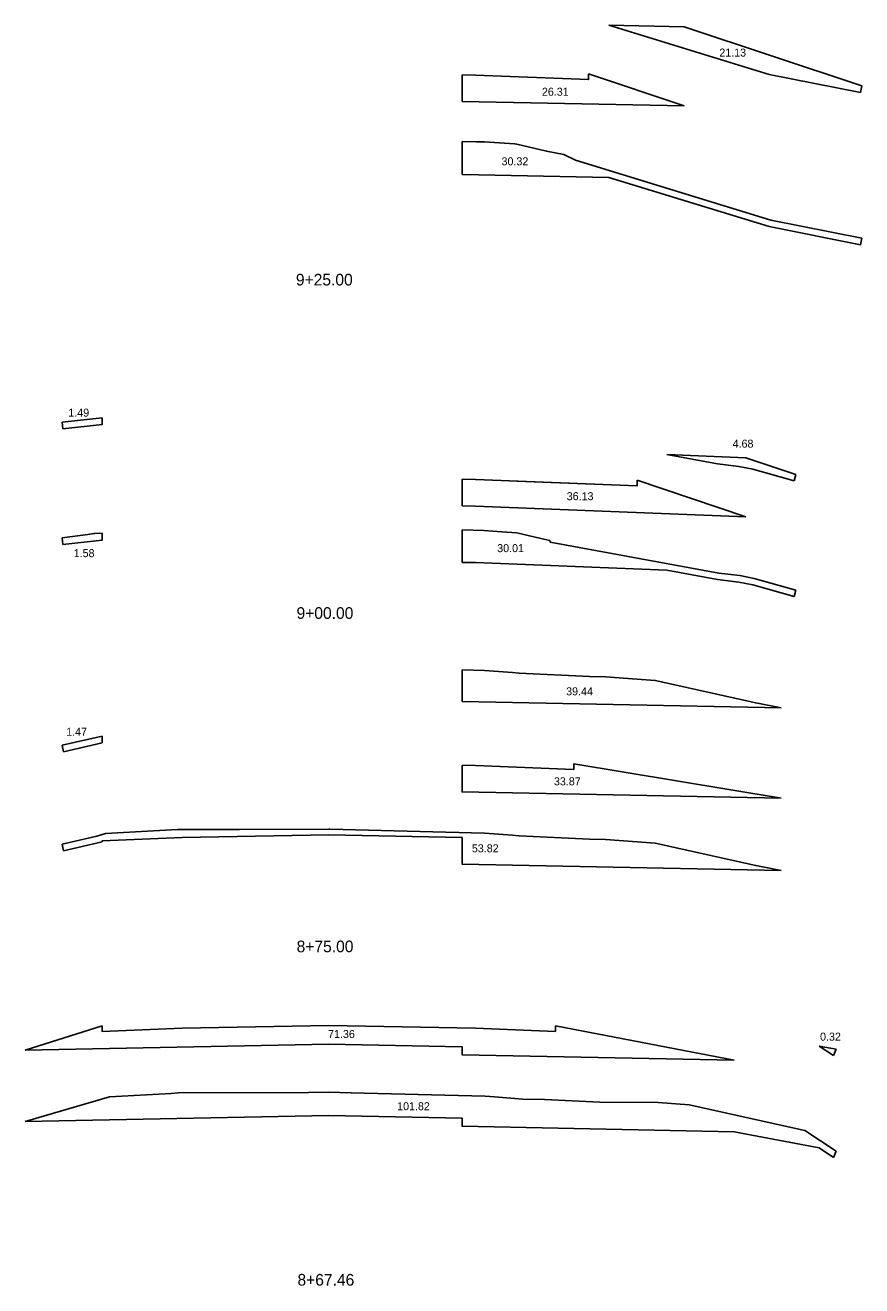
# Model space of a CAD drawing. Extents: x 2194502 to 2194968, y 863888 to 863998.
# Drawn here: x 2194501.8 to 2194564.5, y 863893.6 to 863988.1 of the extents above; entities that cross this region are included whole.
import ezdxf

# ---------------------------------------------------------------- set-up
doc = ezdxf.new("R2010")
doc.units = 0
for name, color, linetype in [('Approach', 7, 'Continuous'), ('H_V ANNOTATION', 7, 'Continuous'), ('S_Roadway_Centerline', 7, 'Continuous'), ('TEMPLATE', 7, 'Continuous')]:
    doc.layers.add(name, color=color, linetype=linetype)

msp = doc.modelspace()

# ---------------------------------------------------------------- linework, layer by layer
at = {"layer": 'S_Roadway_Centerline'}
for points in [[(2194534.524, 863979.373), (2194535.609, 863979.357), (2194536.106, 863979.345), (2194536.216, 863979.336), (2194538.461, 863979.202), (2194538.62, 863979.165), (2194540.858, 863978.645), (2194540.86, 863978.635), (2194542.158, 863978.397), (2194543.036, 863977.964), (2194557.68, 863973.475), (2194564.506, 863972.121)], [(2194534.524, 863950.236), (2194536.155, 863950.194), (2194537.501, 863950.091), (2194538.622, 863950.024), (2194540.427, 863949.608), (2194541.097, 863949.453), (2194541.119, 863949.331), (2194553.77, 863947.01), (2194555.369, 863946.816), (2194556.443, 863946.609), (2194559.558, 863945.722)], [(2194504.524, 863949.647), (2194506.444, 863949.897), (2194506.902, 863949.963), (2194506.973, 863949.967), (2194507.524, 863949.986)], [(2194534.524, 863939.741), (2194536.204, 863939.698), (2194538.303, 863939.538), (2194538.785, 863939.503), (2194538.798, 863939.503), (2194544.077, 863939.238), (2194545.276, 863939.227), (2194549.015, 863938.952), (2194556.553, 863937.272), (2194558.464, 863936.904)], [(2194504.524, 863926.674), (2194507.128, 863927.277), (2194507.765, 863927.464), (2194513.168, 863927.765), (2194513.186, 863927.767), (2194517.836, 863927.777), (2194524.524, 863927.798), (2194524.61, 863927.797), (2194536.204, 863927.501), (2194538.303, 863927.341), (2194538.785, 863927.305), (2194538.798, 863927.305), (2194544.077, 863927.04), (2194545.276, 863927.03), (2194549.015, 863926.755), (2194556.553, 863925.075), (2194558.464, 863924.707)], [(2194501.751, 863905.867), (2194508.083, 863907.726), (2194512.709, 863907.983), (2194513.232, 863908.025), (2194523.012, 863908.045), (2194524.505, 863908.066), (2194526.192, 863908.027), (2194536.247, 863907.77), (2194536.957, 863907.72), (2194539.087, 863907.563), (2194540.696, 863907.54), (2194544.868, 863907.33), (2194549.22, 863907.293), (2194551.56, 863907.121), (2194560.239, 863905.192), (2194562.582, 863903.65)]]:
    msp.add_lwpolyline(points, dxfattribs=at)
at = {"layer": 'TEMPLATE'}
for p, q in [((2194551.183, 863987.977), (2194545.533, 863988.09)), ((2194535.524, 863984.355), (2194534.524, 863984.375)), ((2194534.524, 863982.375), (2194534.524, 863984.375)), ((2194564.506, 863983.536), (2194564.409, 863983.045)), ((2194551.183, 863982.042), (2194534.524, 863982.375)), ((2194534.524, 863976.896), (2194534.524, 863979.373)), ((2194545.533, 863976.676), (2194534.524, 863976.896)), ((2194564.506, 863972.121), (2194564.409, 863971.631)), ((2194507.524, 863958.642), (2194504.524, 863958.322)), ((2194504.524, 863958.322), (2194504.576, 863957.828)), ((2194555.819, 863955.653), (2194549.877, 863955.891)), ((2194555.819, 863955.653), (2194559.558, 863954.397)), ((2194535.524, 863954.03), (2194534.524, 863954.05)), ((2194547.654, 863953.544), (2194535.524, 863954.03)), ((2194547.654, 863953.961), (2194555.819, 863951.218)), ((2194559.558, 863954.397), (2194559.421, 863953.916)), ((2194535.524, 863952.03), (2194534.524, 863952.05)), ((2194555.819, 863951.218), (2194535.524, 863952.03)), ((2194504.524, 863949.647), (2194504.576, 863949.153)), ((2194535.524, 863947.79), (2194534.524, 863947.81)), ((2194549.877, 863947.216), (2194535.524, 863947.79)), ((2194559.558, 863945.722), (2194559.421, 863945.241)), ((2194507.524, 863934.764), (2194504.524, 863934.096)), ((2194504.524, 863934.096), (2194504.632, 863933.608)), ((2194535.524, 863932.579), (2194534.524, 863932.599)), ((2194542.912, 863932.7), (2194558.464, 863930.12)), ((2194504.524, 863926.674), (2194504.632, 863926.186)), ((2194513.524, 863927.165), (2194524.524, 863927.385)), ((2194534.524, 863927.185), (2194524.524, 863927.385)), ((2194507.524, 863913.044), (2194501.751, 863911.232)), ((2194513.524, 863912.868), (2194524.524, 863913.088)), ((2194535.524, 863912.868), (2194524.524, 863913.088)), ((2194541.524, 863913.044), (2194554.923, 863910.48)), ((2194501.751, 863911.232), (2194524.524, 863911.688)), ((2194534.524, 863911.488), (2194524.524, 863911.688)), ((2194561.303, 863911.538), (2194562.585, 863911.292)), ((2194562.582, 863911.294), (2194562.39, 863910.822)), ((2194501.751, 863905.867), (2194524.524, 863906.323)), ((2194534.524, 863906.123), (2194524.524, 863906.323)), ((2194554.923, 863905.115), (2194561.303, 863903.894)), ((2194562.582, 863903.65), (2194562.39, 863903.178))]:
    msp.add_line(p, q, dxfattribs=at)
for points in [[(2194545.533, 863988.09), (2194557.558, 863984.404), (2194564.409, 863983.045)], [(2194551.183, 863987.977), (2194564.506, 863983.536)], [(2194544.012, 863984.432), (2194544.012, 863984.015), (2194535.524, 863984.355)], [(2194544.012, 863984.432), (2194551.183, 863982.042)], [(2194545.533, 863976.676), (2194557.558, 863972.989), (2194564.409, 863971.631)], [(2194507.524, 863958.642), (2194507.524, 863958.142), (2194504.576, 863957.828)], [(2194549.877, 863955.891), (2194553.694, 863955.19), (2194555.291, 863954.997), (2194556.327, 863954.798), (2194559.421, 863953.916)], [(2194534.524, 863952.05), (2194534.524, 863954.05)], [(2194547.654, 863953.961), (2194547.654, 863953.544), (2194538.622, 863953.906)], [(2194534.524, 863947.81), (2194534.524, 863950.236)], [(2194507.524, 863949.986), (2194507.524, 863949.467), (2194504.576, 863949.153)], [(2194549.877, 863947.216), (2194553.694, 863946.515), (2194555.291, 863946.322), (2194556.327, 863946.123), (2194559.421, 863945.241)], [(2194558.464, 863936.904), (2194534.524, 863937.383), (2194534.524, 863939.741)], [(2194504.632, 863933.608), (2194507.524, 863934.278), (2194507.524, 863934.764)], [(2194558.464, 863930.12), (2194534.524, 863930.599), (2194534.524, 863932.599)], [(2194542.912, 863932.7), (2194542.912, 863932.284), (2194535.524, 863932.579)], [(2194504.632, 863926.186), (2194507.524, 863926.856), (2194507.524, 863926.925)], [(2194507.524, 863926.925), (2194507.524, 863926.925), (2194513.524, 863927.165)], [(2194558.464, 863924.707), (2194534.524, 863925.185), (2194534.524, 863927.185)], [(2194507.524, 863912.628), (2194507.524, 863913.044), (2194507.524, 863912.628), (2194513.524, 863912.868)], [(2194541.524, 863913.044), (2194541.524, 863912.628), (2194535.524, 863912.868)], [(2194554.923, 863910.48), (2194534.524, 863910.888), (2194534.524, 863911.488)], [(2194561.303, 863911.538), (2194562.39, 863910.822)], [(2194554.923, 863905.115), (2194534.524, 863905.523), (2194534.524, 863906.123)], [(2194561.303, 863903.894), (2194562.39, 863903.178)]]:
    msp.add_lwpolyline(points, dxfattribs=at)

# ---------------------------------------------------------------- texts
at = {"layer": 'Approach'}
for s, p in [('21.13', (2194553.819, 863985.737)), ('26.31', (2194540.511, 863982.802)), ('30.32', (2194537.482, 863977.583)), ('1.49', (2194504.985, 863958.733)), ('4.68', (2194554.817, 863956.41)), ('36.13', (2194542.372, 863952.471)), ('30.01', (2194537.157, 863948.574)), ('1.58', (2194505.39, 863948.202)), ('39.44', (2194542.329, 863937.837)), ('1.47', (2194504.822, 863934.804)), ('33.87', (2194541.413, 863931.086)), ('53.82', (2194535.256, 863926.064)), ('71.36', (2194524.47, 863912.138)), ('0.32', (2194561.375, 863911.942)), ('101.82', (2194529.651, 863906.724))]:
    msp.add_text(s, height=0.6, dxfattribs=at).set_placement(p)
at = {"layer": 'H_V ANNOTATION'}
for s, p in [('9+25.00', (2194522.058, 863968.571)), ('9+00.00', (2194522.105, 863943.571)), ('8+75.00', (2194522.112, 863918.571)), ('8+67.46', (2194522.175, 863893.571))]:
    msp.add_text(s, height=0.875, dxfattribs=at).set_placement(p)

doc.saveas('drawing.dxf')
